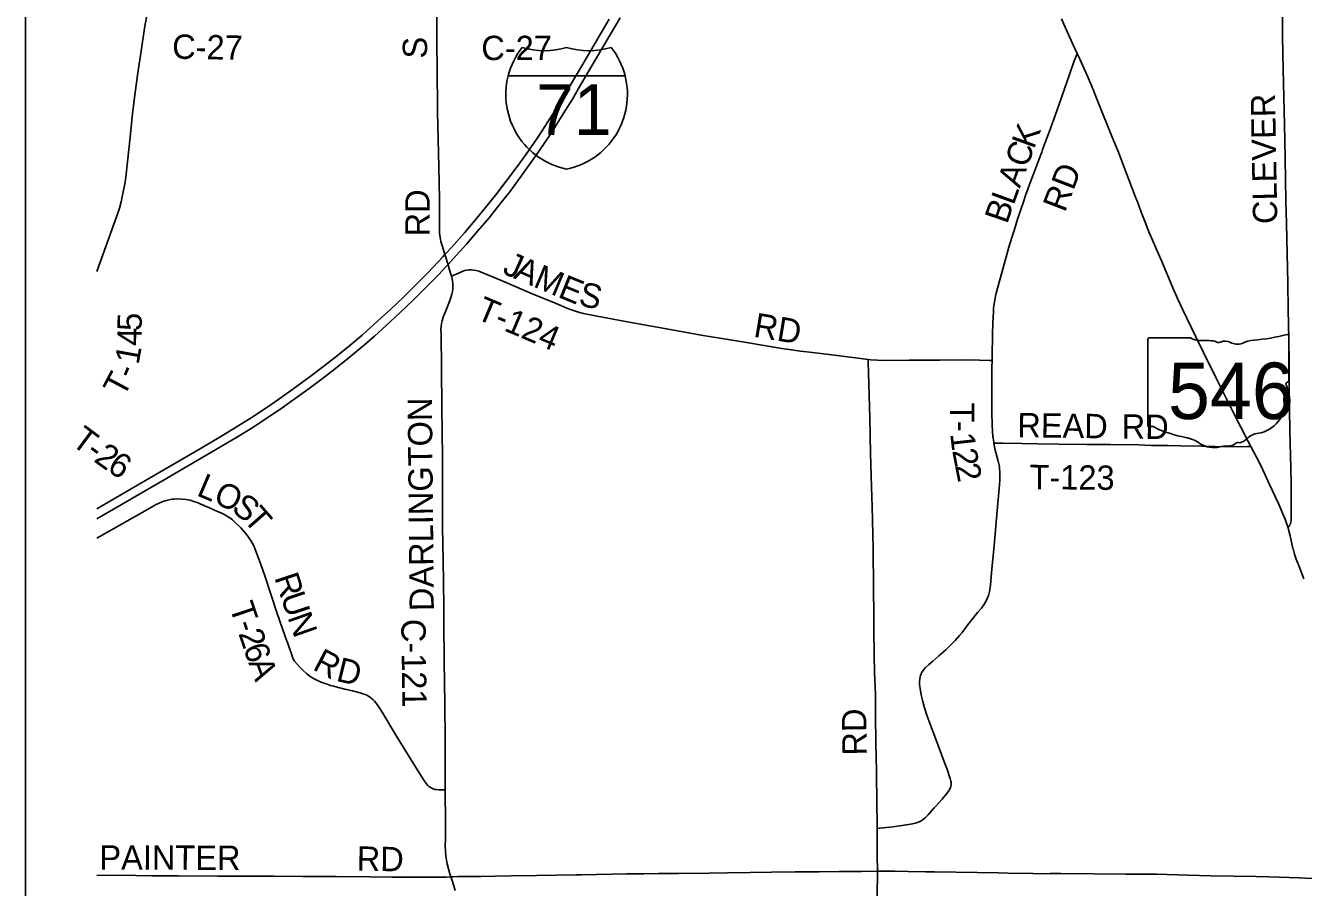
# Model space of a CAD drawing. Extents: x 40529 to 41139, y 15164 to 15584.
# Drawn here: x 40528.7 to 40618.2, y 15261.3 to 15321.7 of the extents above; entities that cross this region are included whole.
import ezdxf

# ---------------------------------------------------------------- set-up
doc = ezdxf.new("R2010")
doc.units = 0
for name, color, linetype in [('GM_X_County_Road', 7, 'Continuous'), ('GM_X_County_Road_Text', 7, 'Continuous'), ('GM_X_Interstate_Location', 7, 'Continuous'), ('GM_X_Interstate_Route', 7, 'Continuous'), ('GM_X_Interstate_Shield', 7, 'Continuous'), ('GM_X_State_Location', 7, 'Continuous'), ('GM_X_State_Route', 7, 'Continuous'), ('GM_X_State_Shield', 7, 'Continuous'), ('GM_X_Township_Road', 7, 'Continuous'), ('GM_X_Township_Road_Text', 7, 'Continuous'), ('SC_Scratch1', 7, 'Continuous')]:
    doc.layers.add(name, color=color, linetype=linetype)

msp = doc.modelspace()

# ---------------------------------------------------------------- linework, layer by layer
at = {"layer": 'GM_X_County_Road'}
for points in [[(40558.508, 15304.131), (40558.43, 15304.425), (40558.332, 15304.752), (40558.268, 15304.959), (40558.214, 15305.138), (40558.109, 15305.476), (40558.056, 15305.644), (40557.881, 15306.207), (40557.764, 15306.556), (40557.707, 15306.85), (40557.678, 15307.139), (40557.678, 15307.489), (40557.681, 15308.063), (40557.669, 15309.554), (40557.616, 15311.798), (40557.526, 15315.615), (40557.503, 15318.878), (40557.493, 15320.237), (40557.474, 15321.767), (40557.479, 15322.434)], [(40558.068, 15268.159), (40558.073, 15268.406), (40558.073, 15269.627), (40558.068, 15271.666), (40558.035, 15274.175), (40557.996, 15277.154), (40557.988, 15277.99), (40557.975, 15279.015), (40557.966, 15280.843), (40557.94, 15282.813), (40557.906, 15285.405), (40557.887, 15286.521), (40557.887, 15289.037), (40557.89, 15290.619), (40557.887, 15291.457), (40557.825, 15294.997), (40557.806, 15297.595), (40557.78, 15300.111), (40557.773, 15300.385), (40557.783, 15300.627), (40557.811, 15300.821), (40557.849, 15301.015), (40557.925, 15301.276), (40558.166, 15301.833), (40558.403, 15302.44), (40558.492, 15302.703), (40558.54, 15302.882), (40558.577, 15303.062), (40558.599, 15303.245), (40558.607, 15303.428), (40558.6, 15303.612), (40558.578, 15303.794), (40558.525, 15304.066), (40558.508, 15304.131)], [(40558.471, 15262.046), (40558.401, 15262.276), (40558.22, 15262.964), (40558.126, 15263.499), (40558.097, 15263.85), (40558.078, 15264.219), (40558.087, 15264.693), (40558.087, 15264.863), (40558.097, 15265.332), (40558.092, 15265.597), (40558.087, 15265.801), (40558.068, 15268.159)], [(40558.77, 15261.094), (40558.575, 15261.738), (40558.471, 15262.046)]]:
    msp.add_lwpolyline(points, dxfattribs=at)
at = {"layer": 'GM_X_Interstate_Route'}
for points in [[(40533.651, 15287.14), (40538.363, 15289.869), (40542.713, 15292.403), (40543.512, 15292.882), (40544.46, 15293.476), (40545.631, 15294.24), (40546.636, 15294.916), (40547.552, 15295.556), (40548.534, 15296.266), (40549.655, 15297.102), (40550.39, 15297.674), (40551.331, 15298.438), (40552.404, 15299.334), (40553.109, 15299.942), (40553.943, 15300.687), (40554.901, 15301.574), (40555.843, 15302.476), (40556.768, 15303.396), (40557.613, 15304.264), (40558.081, 15304.761), (40558.268, 15304.959), (40558.635, 15305.349), (40559.57, 15306.389), (40560.365, 15307.303), (40561.144, 15308.232), (40561.906, 15309.174), (40562.593, 15310.056), (40563.211, 15310.874), (40563.922, 15311.855), (40564.617, 15312.847), (40565.498, 15314.164), (40566.34, 15315.507), (40566.984, 15316.534), (40567.405, 15317.278), (40568.579, 15319.272), (40569.583, 15320.962), (40570.331, 15322.227)], [(40533.651, 15287.839), (40536.61, 15289.566), (40540.964, 15292.09), (40542.33, 15292.895), (40543.605, 15293.669), (40544.472, 15294.217), (40545.562, 15294.935), (40546.408, 15295.516), (40547.397, 15296.216), (40548.601, 15297.097), (40549.568, 15297.828), (40550.522, 15298.576), (40551.387, 15299.287), (40552.238, 15300.012), (40553.357, 15301), (40554.252, 15301.817), (40555.132, 15302.65), (40555.998, 15303.5), (40556.848, 15304.364), (40557.939, 15305.515), (40558.056, 15305.644), (40558.161, 15305.76), (40558.502, 15306.137), (40559.428, 15307.184), (40560.158, 15308.033), (40560.812, 15308.823), (40561.624, 15309.845), (40562.421, 15310.879), (40563.143, 15311.852), (40563.74, 15312.687), (40564.533, 15313.839), (40565.097, 15314.696), (40565.748, 15315.719), (40566.77, 15317.388), (40567.728, 15318.988), (40569.555, 15322.137)]]:
    msp.add_lwpolyline(points, dxfattribs=at)
at = {"layer": 'GM_X_Interstate_Shield'}
for p, q in [((40562.485, 15318.162), (40570.682, 15318.162)), ((40570.682, 15318.162), (40562.485, 15318.162)), ((40570.682, 15318.162), (40562.485, 15318.162))]:
    msp.add_line(p, q, dxfattribs=at)
for centre, start, end in [((40567.649, 15316.856), 141.66896, 165.80665), ((40565.027, 15325.254), 253.00908, 286.99093), ((40568.14, 15325.254), 253.00908, 286.99093), ((40565.518, 15316.856), 14.19335, 38.33104), ((40567.649, 15316.856), 165.80665, 258.46304), ((40565.518, 15316.856), 281.53696, 14.19335)]:
    msp.add_arc(centre, 5.327, start, end, dxfattribs=at)
at = {"layer": 'GM_X_State_Route'}
for points in [[(40617.156, 15286.511), (40617.081, 15286.757), (40616.953, 15287.112), (40616.775, 15287.545), (40616.48, 15288.2), (40615.866, 15289.552), (40615.395, 15290.574), (40615.103, 15291.163), (40614.542, 15292.199), (40614.354, 15292.548), (40613.345, 15294.569), (40613.247, 15294.753), (40612.087, 15297.038), (40611.225, 15298.799), (40610.698, 15299.878), (40609.77, 15301.824), (40609.411, 15302.578), (40609.025, 15303.43), (40608.304, 15305.155), (40607.725, 15306.488), (40607.508, 15306.992), (40607.409, 15307.237), (40607.136, 15307.92), (40606.862, 15308.627), (40606.693, 15309.088), (40606.618, 15309.272), (40606.552, 15309.46), (40606.49, 15309.606), (40606.401, 15309.861), (40605.656, 15311.811), (40605.275, 15312.819), (40605.204, 15312.984), (40604.837, 15313.879), (40603.824, 15316.367), (40603.371, 15317.502), (40603.084, 15318.185), (40602.467, 15319.556), (40602.381, 15319.741), (40602.057, 15320.442), (40601.533, 15321.579), (40601.272, 15322.171)], [(40617.502, 15285.059), (40617.302, 15285.935), (40617.194, 15286.388), (40617.156, 15286.511)], [(40618.267, 15282.927), (40617.927, 15283.789), (40617.731, 15284.316), (40617.607, 15284.66), (40617.509, 15285.029), (40617.502, 15285.059)]]:
    msp.add_lwpolyline(points, dxfattribs=at)
at = {"layer": 'GM_X_State_Shield'}
for p, q in [((40607.32, 15299.709), (40607.32, 15293.705)), ((40610.313, 15299.812), (40607.417, 15299.812)), ((40617.208, 15296.82), (40617.208, 15299.961)), ((40617.207, 15296.821), (40617.208, 15296.82))]:
    msp.add_line(p, q, dxfattribs=at)
for centre, major_axis, start_param, end_param in [((40607.433, 15299.721), (0.115, 0), 1.712693, 3.28349), ((40611.003, 15300.509), (1.111, 0), 4.042523, 4.731795), ((40613.686, 15307.997), (10.486, 0), 4.814394, 5.042369), ((40617.098, 15299.974), (0.11, 0), 6.141152, 7.989035), ((40611.371, 15296.441), (3.989, 0), 1.404758, 1.657858), ((40612.277, 15299.753), (0.321, 0), 3.836095, 5.185415), ((40612.747, 15299.059), (0.666, 0), 0.950623, 2.079405), ((40613.607, 15300.01), (0.802, 0), 4.081561, 5.145723), ((40615.023, 15297.978), (2.11, 0), 1.699011, 2.107814), ((40617.182, 15296.59), (0.17, 0), 1.883978, 3.671073), ((40616.098, 15296.193), (1.023, 0), 5.934695, 6.695948), ((40617.09, 15296.808), (0.118, 0), 5.05454, 6.418171), ((40614.273, 15295.106), (2.623, 0), 5.101752, 6.440018), ((40617.602, 15295.506), (0.744, 0), 2.387724, 3.262537), ((40607.434, 15293.692), (0.116, 0), 3.00124, 4.508301), ((40607.452, 15294.306), (0.882, 0), 4.665946, 4.897461), ((40607.632, 15293.359), (0.318, 0), 0.519207, 1.627899), ((40611.647, 15298.753), (7.572, 0), 4.195997, 4.488961), ((40609.39, 15291.008), (2.369, 0), 0.823519, 1.323587), ((40613.559, 15293.123), (0.847, 0), 4.937069, 5.64225), ((40615.379, 15292.02), (1.436, 0), 1.647645, 2.488434), ((40611.952, 15293.329), (1.503, 0), 4.026481, 4.996735), ((40612.821, 15291.253), (1.235, 0), 1.495662, 1.94098), ((40612.93, 15292.879), (0.801, 0), 4.691044, 5.507374), ((40613.655, 15292.298), (0.226, 0), 1.147584, 2.315152)]:
    msp.add_ellipse(centre, major_axis=major_axis, ratio=0.8, start_param=start_param, end_param=end_param, dxfattribs=at)
at = {"layer": 'GM_X_Township_Road'}
for points in [[(40533.651, 15304.458), (40535.13, 15308.547), (40535.239, 15308.902), (40535.351, 15309.354), (40535.524, 15310.173), (40535.623, 15310.722), (40535.702, 15311.275), (40535.995, 15313.866), (40536.16, 15315.532), (40536.316, 15316.827), (40536.504, 15318.212), (40536.773, 15320.058), (40536.966, 15321.349), (40537.033, 15321.779), (40537.074, 15321.999), (40537.106, 15322.132), (40537.157, 15322.348), (40537.189, 15322.536)], [(40617.388, 15287.456), (40617.373, 15288.667), (40617.372, 15289.598), (40617.354, 15290.713), (40617.283, 15293.315), (40617.246, 15296.387), (40617.233, 15298.064), (40617.207, 15299.738), (40617.168, 15301.787), (40617.139, 15303.647), (40617.048, 15307.824), (40617.01, 15309.407), (40616.974, 15310.896), (40616.947, 15312.384), (40616.931, 15313.687), (40616.893, 15315.73), (40616.825, 15318.614), (40616.779, 15320.928), (40616.774, 15322.034), (40616.766, 15322.35)], [(40596.407, 15298.231), (40596.41, 15298.396), (40596.437, 15300.151), (40596.489, 15301.39), (40596.498, 15301.527), (40596.517, 15301.922), (40596.55, 15302.205), (40596.599, 15302.477), (40596.674, 15302.843), (40596.789, 15303.295), (40597.112, 15304.454), (40597.586, 15306.172), (40597.794, 15306.85), (40597.951, 15307.339), (40598.202, 15308.126), (40598.607, 15309.351), (40598.748, 15309.784), (40599.042, 15310.567), (40599.405, 15311.538), (40599.822, 15312.657), (40599.894, 15312.828), (40599.956, 15313.004), (40600.441, 15314.303), (40600.956, 15315.722), (40601.826, 15318.255), (40602.17, 15319.221), (40602.276, 15319.481), (40602.381, 15319.741)], [(40558.508, 15304.131), (40558.678, 15304.202), (40558.914, 15304.302), (40559.251, 15304.458), (40559.431, 15304.525), (40559.587, 15304.558), (40559.72, 15304.572), (40559.882, 15304.569), (40560.066, 15304.555), (40560.247, 15304.525), (40560.425, 15304.479), (40560.599, 15304.417), (40562.063, 15303.811), (40564.121, 15302.933), (40565.842, 15302.215), (40566.704, 15301.859), (40567.055, 15301.731), (40567.413, 15301.62), (40567.776, 15301.527), (40568.232, 15301.429), (40570.706, 15300.964), (40572.269, 15300.679), (40573.585, 15300.45), (40574.227, 15300.337), (40576.164, 15299.988), (40577.906, 15299.695), (40579.194, 15299.491), (40581.677, 15299.08), (40582.505, 15298.963), (40582.96, 15298.893), (40583.419, 15298.827), (40585.175, 15298.615), (40587.571, 15298.314), (40587.719, 15298.297)], [(40588.352, 15265.45), (40588.348, 15265.821), (40588.332, 15267.124), (40588.303, 15269.455), (40588.266, 15271.412), (40588.243, 15273.365), (40588.237, 15274.294), (40588.235, 15274.854), (40588.186, 15275.876), (40588.172, 15276.338), (40588.153, 15277.64), (40588.126, 15279.317), (40588.12, 15280.435), (40588.102, 15282.207), (40588.067, 15285.097), (40588.054, 15286.029), (40588.026, 15287.053), (40587.995, 15287.984), (40587.958, 15289.382), (40587.885, 15291.71), (40587.831, 15294.218), (40587.724, 15298.131), (40587.719, 15298.297)], [(40587.719, 15298.297), (40587.912, 15298.276), (40588.37, 15298.25), (40589.013, 15298.238), (40590.596, 15298.248), (40592.753, 15298.262), (40594.511, 15298.281), (40595.537, 15298.262), (40596.232, 15298.235), (40596.407, 15298.231)], [(40596.541, 15292.43), (40596.524, 15292.53), (40596.468, 15292.904), (40596.433, 15293.254), (40596.407, 15293.726), (40596.39, 15294.589), (40596.387, 15294.696), (40596.397, 15295.417), (40596.397, 15296.056), (40596.397, 15297.727), (40596.407, 15298.231)], [(40588.352, 15265.45), (40588.529, 15265.463), (40588.805, 15265.484), (40589.45, 15265.565), (40590.554, 15265.718), (40590.828, 15265.769), (40591.007, 15265.813), (40591.182, 15265.87), (40591.35, 15265.943), (40591.431, 15265.986), (40591.585, 15266.085), (40591.728, 15266.2), (40591.918, 15266.409), (40592.213, 15266.729), (40592.358, 15266.888), (40592.468, 15267.007), (40592.917, 15267.508), (40593.243, 15267.899), (40593.36, 15268.061), (40593.441, 15268.194), (40593.479, 15268.277), (40593.502, 15268.332), (40593.518, 15268.375), (40593.527, 15268.416), (40593.54, 15268.5), (40593.546, 15268.594), (40593.54, 15268.681), (40593.524, 15268.769), (40593.474, 15268.946), (40593.38, 15269.205), (40593.298, 15269.466), (40593.237, 15269.64), (40593.097, 15269.987), (40592.387, 15271.896), (40592.089, 15272.676), (40591.842, 15273.375), (40591.672, 15273.901), (40591.547, 15274.349), (40591.444, 15274.803), (40591.364, 15275.254), (40591.33, 15275.526), (40591.323, 15275.712), (40591.335, 15275.9), (40591.37, 15276.086), (40591.398, 15276.176), (40591.431, 15276.265), (40591.473, 15276.349), (40591.52, 15276.428), (40591.629, 15276.579), (40591.754, 15276.719), (40591.962, 15276.918), (40592.249, 15277.169), (40592.676, 15277.538), (40593.16, 15277.971), (40593.63, 15278.417), (40593.825, 15278.616), (40594.132, 15278.963), (40594.307, 15279.179), (40594.759, 15279.77), (40594.872, 15279.91), (40595.415, 15280.588), (40595.657, 15280.889), (40595.822, 15281.118), (40595.964, 15281.348), (40596.084, 15281.597), (40596.152, 15281.768), (40596.226, 15282.039), (40596.275, 15282.314), (40596.294, 15282.518), (40596.401, 15283.607), (40596.546, 15285.264), (40596.824, 15288.231), (40596.934, 15289.53), (40596.952, 15289.898), (40596.95, 15290.356), (40596.926, 15290.722), (40596.901, 15290.903), (40596.842, 15291.173), (40596.604, 15292.052), (40596.541, 15292.43)], [(40596.541, 15292.43), (40596.685, 15292.43), (40597.192, 15292.432), (40598.496, 15292.403), (40599.607, 15292.39), (40601.092, 15292.367), (40603.044, 15292.353), (40604.715, 15292.333), (40606.666, 15292.311), (40607.594, 15292.286), (40608.707, 15292.275), (40609.636, 15292.259), (40611.122, 15292.22), (40612.055, 15292.209), (40613.633, 15292.19), (40614.316, 15292.195), (40614.542, 15292.199)], [(40533.651, 15285.777), (40537.358, 15287.893), (40537.765, 15288.118), (40538.015, 15288.239), (40538.271, 15288.345), (40538.446, 15288.407), (40538.623, 15288.455), (40538.895, 15288.505), (40539.08, 15288.524), (40539.358, 15288.532), (40539.636, 15288.519), (40539.911, 15288.487), (40540.184, 15288.434), (40540.451, 15288.361), (40540.754, 15288.252), (40540.995, 15288.152), (40541.137, 15288.086), (40541.246, 15288.034), (40541.374, 15287.968), (40541.492, 15287.921), (40541.895, 15287.745), (40542.496, 15287.477), (40542.743, 15287.352), (40542.975, 15287.196), (40543.164, 15287.063), (40543.404, 15286.835), (40543.67, 15286.58), (40543.732, 15286.511), (40544.154, 15286.017), (40544.319, 15285.794), (40544.473, 15285.563), (40544.566, 15285.404), (40544.648, 15285.239), (40544.718, 15285.068), (40545.139, 15283.933), (40545.416, 15283.142), (40546.265, 15280.578), (40546.669, 15279.436), (40546.943, 15278.643), (40547.012, 15278.467), (40547.091, 15278.255), (40547.185, 15278.004), (40547.285, 15277.687), (40547.375, 15277.427), (40547.507, 15277.166), (40547.683, 15276.958), (40547.891, 15276.735), (40548.128, 15276.484), (40548.35, 15276.299), (40548.606, 15276.091), (40548.848, 15275.959), (40549.16, 15275.793), (40549.364, 15275.703), (40549.558, 15275.622), (40549.804, 15275.547), (40550.041, 15275.471), (40550.264, 15275.405), (40550.496, 15275.346), (40551.034, 15275.206), (40551.573, 15275.081), (40552.109, 15274.948), (40552.368, 15274.864), (40552.539, 15274.796), (40552.701, 15274.711), (40552.852, 15274.608), (40552.99, 15274.489), (40553.119, 15274.357), (40553.235, 15274.214), (40553.396, 15273.988), (40553.648, 15273.597), (40554.661, 15271.923), (40556.123, 15269.541), (40556.573, 15268.832), (40556.737, 15268.602), (40556.862, 15268.46), (40556.932, 15268.395), (40557.007, 15268.337), (40557.087, 15268.285), (40557.174, 15268.241), (40557.262, 15268.209), (40557.35, 15268.187), (40557.442, 15268.171), (40557.63, 15268.157), (40557.906, 15268.157), (40558.068, 15268.159)], [(40617.156, 15286.511), (40617.243, 15286.639), (40617.3, 15286.723), (40617.351, 15286.906), (40617.366, 15286.996), (40617.382, 15287.178), (40617.388, 15287.456)], [(40588.373, 15262.453), (40588.365, 15263.583), (40588.357, 15265.075), (40588.352, 15265.45)], [(40533.651, 15262.174), (40536.391, 15262.146), (40537.508, 15262.124), (40538.995, 15262.129), (40539.367, 15262.125), (40542.158, 15262.103), (40545.136, 15262.111), (40546.064, 15262.1), (40548.099, 15262.083), (40550.429, 15262.072), (40552.755, 15262.057), (40554.333, 15262.043), (40556.099, 15262.023), (40557.124, 15262.03), (40558.148, 15262.034), (40558.471, 15262.046)], [(40558.471, 15262.046), (40558.628, 15262.06), (40558.973, 15262.088), (40559.816, 15262.092), (40559.909, 15262.09), (40560.561, 15262.085), (40561.585, 15262.097), (40562.702, 15262.118), (40564.471, 15262.15), (40567.251, 15262.203), (40567.624, 15262.209), (40570.792, 15262.259), (40572.003, 15262.264), (40573.028, 15262.282), (40574.425, 15262.295), (40576.567, 15262.321), (40577.871, 15262.347), (40579.455, 15262.363), (40580.942, 15262.394), (40582.609, 15262.406), (40583.727, 15262.405), (40584.286, 15262.414), (40585.679, 15262.427), (40587.262, 15262.438), (40588.373, 15262.453)], [(40588.237, 15246.975), (40588.284, 15247.089), (40588.309, 15247.181), (40588.329, 15247.274), (40588.354, 15247.461), (40588.365, 15247.648), (40588.374, 15248.115), (40588.366, 15249.328), (40588.37, 15250.26), (40588.358, 15252.59), (40588.377, 15254.173), (40588.38, 15255.106), (40588.388, 15256.596), (40588.379, 15257.247), (40588.368, 15258.178), (40588.363, 15260.882), (40588.374, 15262.279), (40588.373, 15262.453)], [(40588.373, 15262.453), (40588.862, 15262.451), (40589.591, 15262.444), (40590.514, 15262.426), (40591.731, 15262.417), (40592.382, 15262.405), (40593.873, 15262.378), (40596.855, 15262.34), (40597.506, 15262.32), (40599.268, 15262.284), (40600.193, 15262.279), (40600.471, 15262.281), (40601.227, 15262.28), (40605.781, 15262.242), (40606.066, 15262.242), (40606.246, 15262.242), (40607.273, 15262.255), (40607.93, 15262.246), (40610.164, 15262.184), (40611.747, 15262.137), (40614.914, 15262.08), (40615.841, 15262.051), (40617.939, 15261.979)], [(40617.939, 15261.979), (40617.969, 15261.978), (40618.354, 15261.964), (40619.005, 15261.952), (40619.844, 15261.955), (40620.864, 15261.969), (40621.699, 15261.986), (40623.736, 15262.049), (40624.263, 15262.079), (40624.475, 15262.091)]]:
    msp.add_lwpolyline(points, dxfattribs=at)
at = {"layer": 'SC_Scratch1'}
msp.add_lwpolyline([(40528.651, 15584.313), (41138.651, 15584.313), (41138.651, 15164.313), (40528.651, 15164.313)], close=True, dxfattribs=at)

# ---------------------------------------------------------------- texts
at = {"layer": 'GM_X_County_Road_Text'}
for s, height, rotation, p in [('C-27', 1.7063, 358.97591, (40538.919, 15319.373)), ('S', 1.706, 90, (40556.802, 15319.383)), ('C-27', 1.7063, 0.00001, (40560.602, 15319.272)), ('RD', 1.7063, 90, (40556.978, 15306.921)), ('DARLINGTON', 1.7063, 90.52188, (40557.278, 15280.679)), ('C-121', 1.7063, 270.81867, (40554.985, 15280.118))]:
    msp.add_text(s, height=height, rotation=rotation, dxfattribs=at).set_placement(p)
at = {"layer": 'GM_X_Interstate_Location'}
for s in ['-', '.', ',']:
    msp.add_text(s, height=0.00568, dxfattribs=at).set_placement((40566.583, 15315.895))
msp.add_text('71', height=0.00568, rotation=0.00001, dxfattribs=at).set_placement((40565.422, 15314.719))
at = {"layer": 'GM_X_Interstate_Shield'}
msp.add_text('71', height=3.5511, dxfattribs=at).set_placement((40564.447, 15314.034))
at = {"layer": 'GM_X_State_Location'}
for s in ['s', 'r']:
    msp.add_text(s, height=0.00568, dxfattribs=at).set_placement((40612.153, 15296.308))
msp.add_text('546', height=0.00568, rotation=0.00001, dxfattribs=at).set_placement((40610.147, 15295.894))
at = {"layer": 'GM_X_State_Shield'}
msp.add_text('546', height=3.9551, dxfattribs=at).set_placement((40608.743, 15294.128))
at = {"layer": 'GM_X_Township_Road_Text'}
for s, height, rotation, p in [('CLEVER', 1.7063, 91.05801, (40616.413, 15307.805)), ('K', 1.706, 69.99267, (40599.343, 15312.979)), ('C', 1.706, 69.99121, (40598.864, 15311.662)), ('A', 1.706, 69.99416, (40598.35, 15310.251)), ('RD', 1.7063, 69.00235, (40601.514, 15308.548)), ('L', 1.706, 70.01652, (40597.914, 15309.051)), ('B', 1.706, 71.08368, (40597.463, 15307.734)), ('J', 1.706, 335.6807, (40562.019, 15304.361)), ('A', 1.706, 337.04513, (40562.79, 15304.013)), ('M', 1.706, 337.14879, (40564.175, 15303.426)), ('E', 1.706, 337.68916, (40565.898, 15302.7)), ('S', 1.706, 346.33747, (40567.346, 15302.129)), ('T-124', 1.7063, 337.02536, (40560.144, 15301.192)), ('RD', 1.7063, 350.61906, (40579.631, 15299.9)), ('5', 1.706, 89.43275, (40536.795, 15300.297)), ('4', 1.706, 89.69424, (40536.789, 15299.248)), ('1', 1.706, 79.68644, (40536.571, 15297.891)), ('T', 1.706, 62.2686, (40535.527, 15295.58)), ('-', 1.706, 67.70579, (40536.196, 15296.869)), ('T', 1.706, 270.04286, (40593.452, 15295.284)), ('READ', 1.7063, 359.25118, (40598.172, 15292.855)), ('RD', 1.7063, 359.51149, (40605.491, 15292.755)), ('T', 1.706, 323.46652, (40531.769, 15292.383)), ('-', 1.706, 270.72201, (40593.453, 15293.985)), ('1', 1.706, 276.35119, (40593.473, 15293.102)), ('-', 1.706, 323.48209, (40532.793, 15291.624)), ('2', 1.706, 324.18253, (40533.37, 15291.198)), ('6', 1.706, 326.91329, (40534.288, 15290.537)), ('2', 1.706, 280.64866, (40593.61, 15291.92)), ('2', 1.706, 281.12875, (40593.807, 15290.871)), ('T-123', 1.7063, 359.4399, (40599.03, 15289.219)), ('L', 1.706, 336.8273, (40540.571, 15288.805)), ('O', 1.706, 335.10503, (40541.732, 15288.308)), ('S', 1.706, 321.78246, (40543.005, 15287.731)), ('T', 1.706, 311.27906, (40543.849, 15287.075)), ('R', 1.706, 288.31462, (40546.074, 15283.032)), ('U', 1.706, 288.36096, (40546.515, 15281.7)), ('T', 1.706, 288.71616, (40542.923, 15280.987)), ('N', 1.706, 289.36832, (40546.998, 15280.245)), ('2', 1.706, 288.75999, (40543.558, 15279.113)), ('-', 1.706, 288.71389, (40543.332, 15279.778)), ('6', 1.706, 288.90215, (40543.897, 15278.114)), ('R', 1.706, 332.25319, (40548.702, 15276.614)), ('D', 1.706, 346.17324, (40550.358, 15275.804)), ('A', 1.706, 290.39186, (40544.254, 15277.074)), ('RD', 1.7063, 90.96876, (40587.634, 15270.569)), ('PAINTER', 1.7063, 359.83814, (40533.828, 15262.565)), ('RD', 1.7063, 359.01636, (40551.858, 15262.49))]:
    msp.add_text(s, height=height, rotation=rotation, dxfattribs=at).set_placement(p)

doc.saveas('drawing.dxf')
